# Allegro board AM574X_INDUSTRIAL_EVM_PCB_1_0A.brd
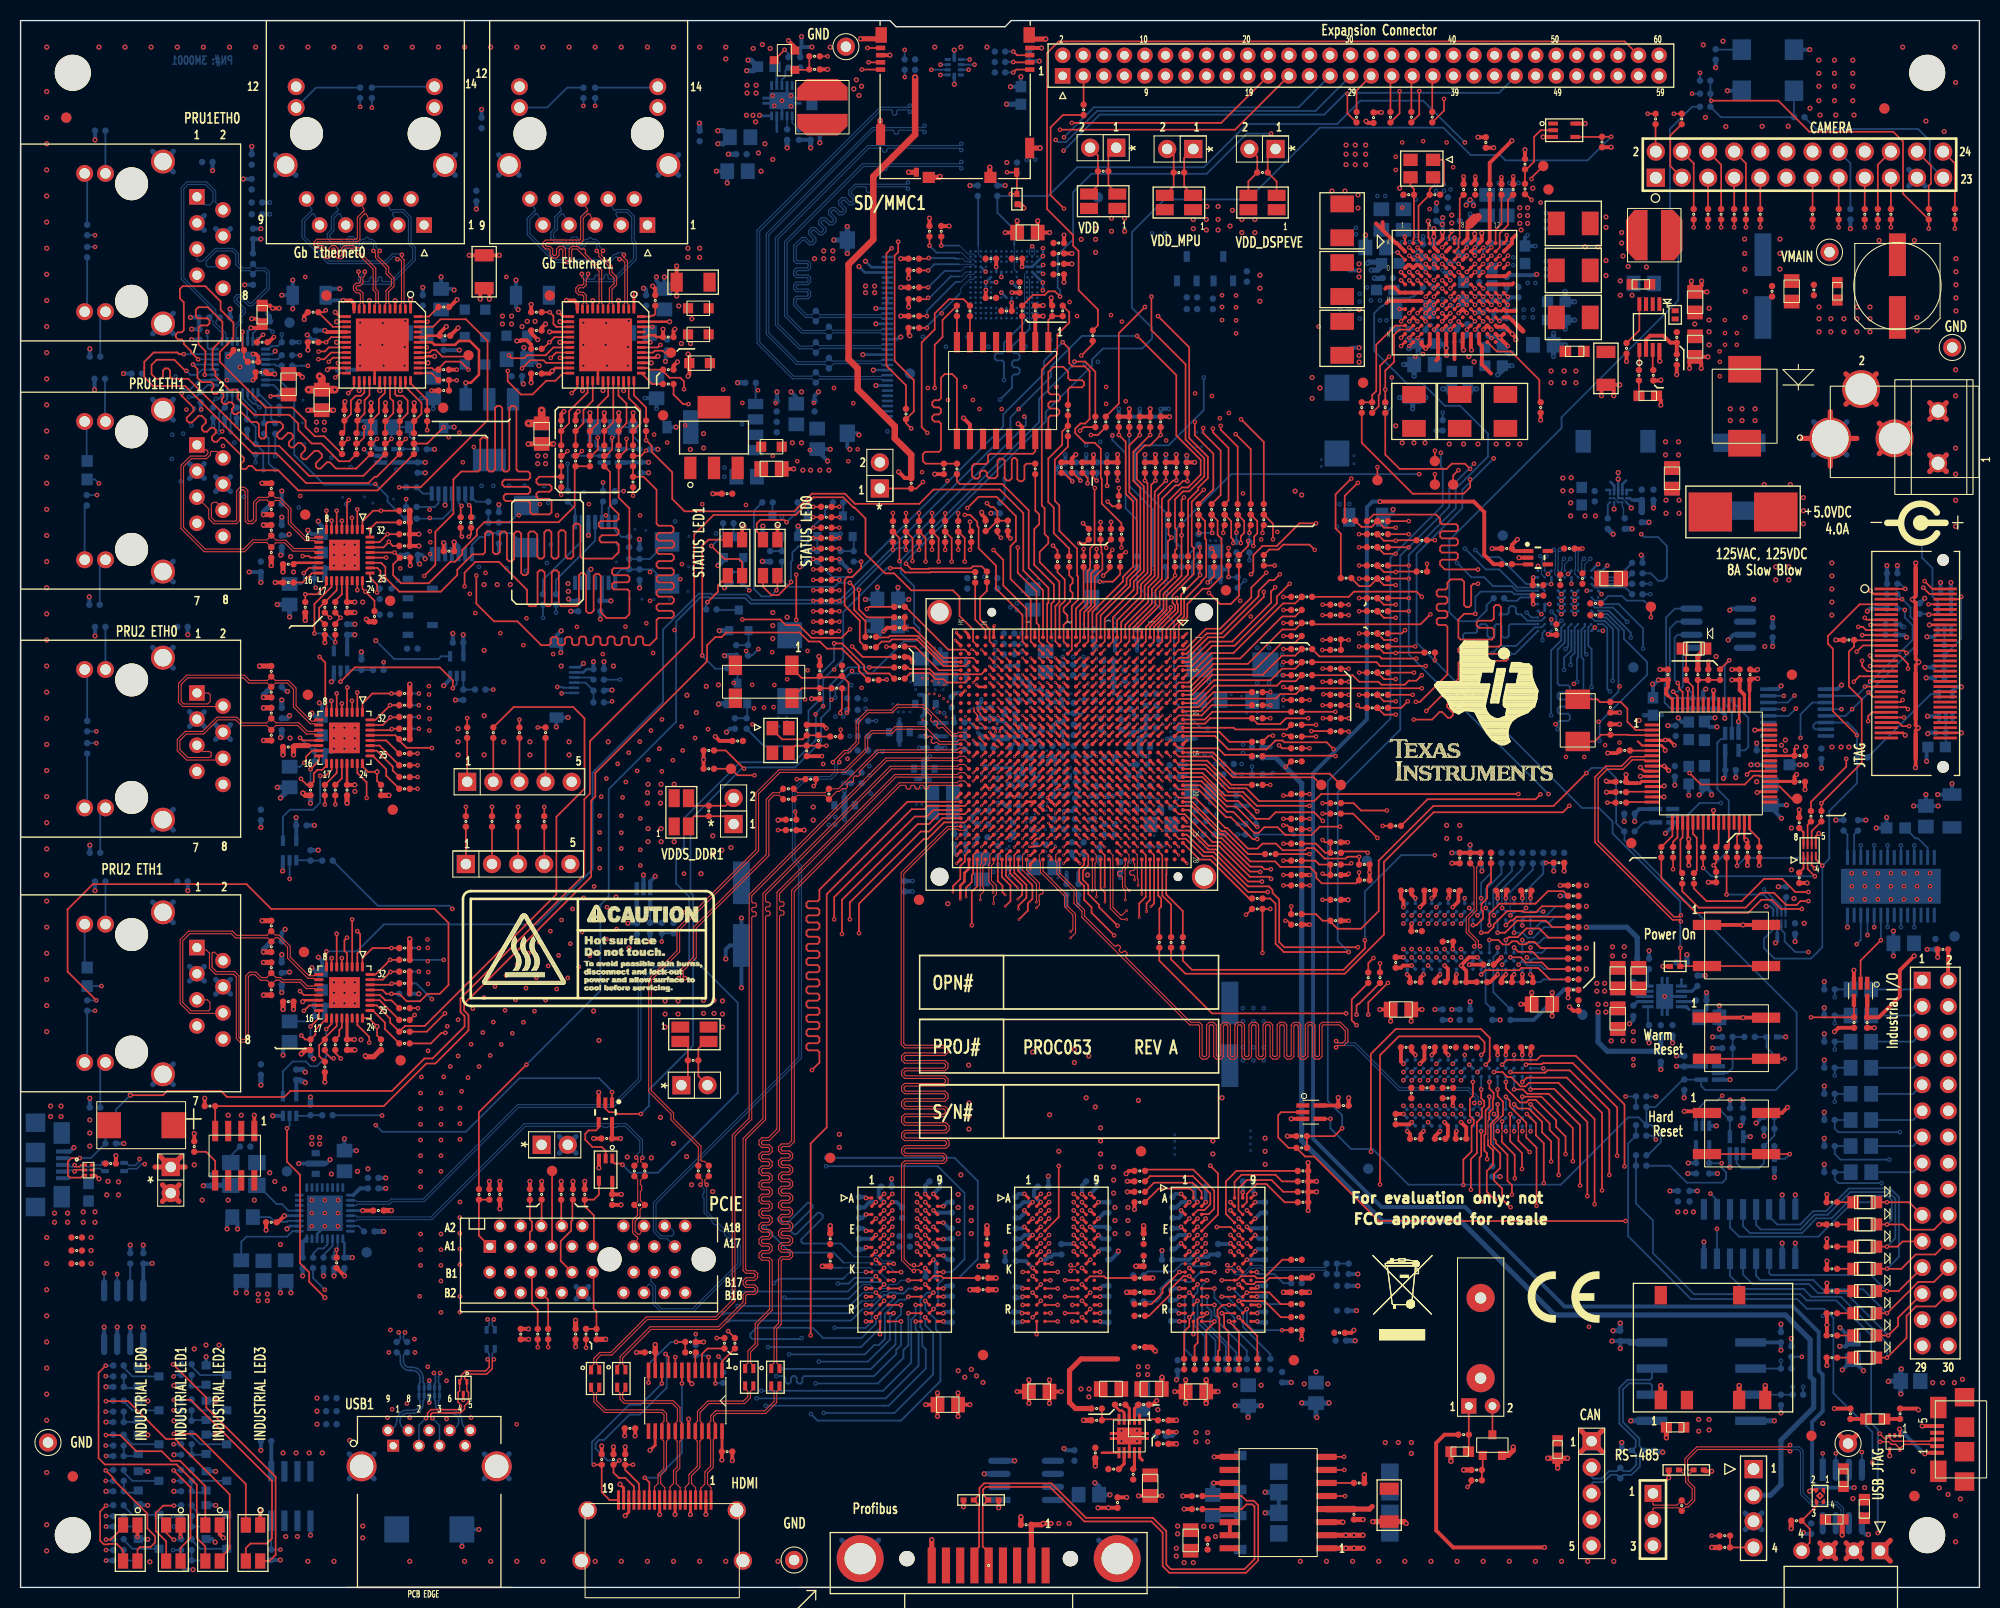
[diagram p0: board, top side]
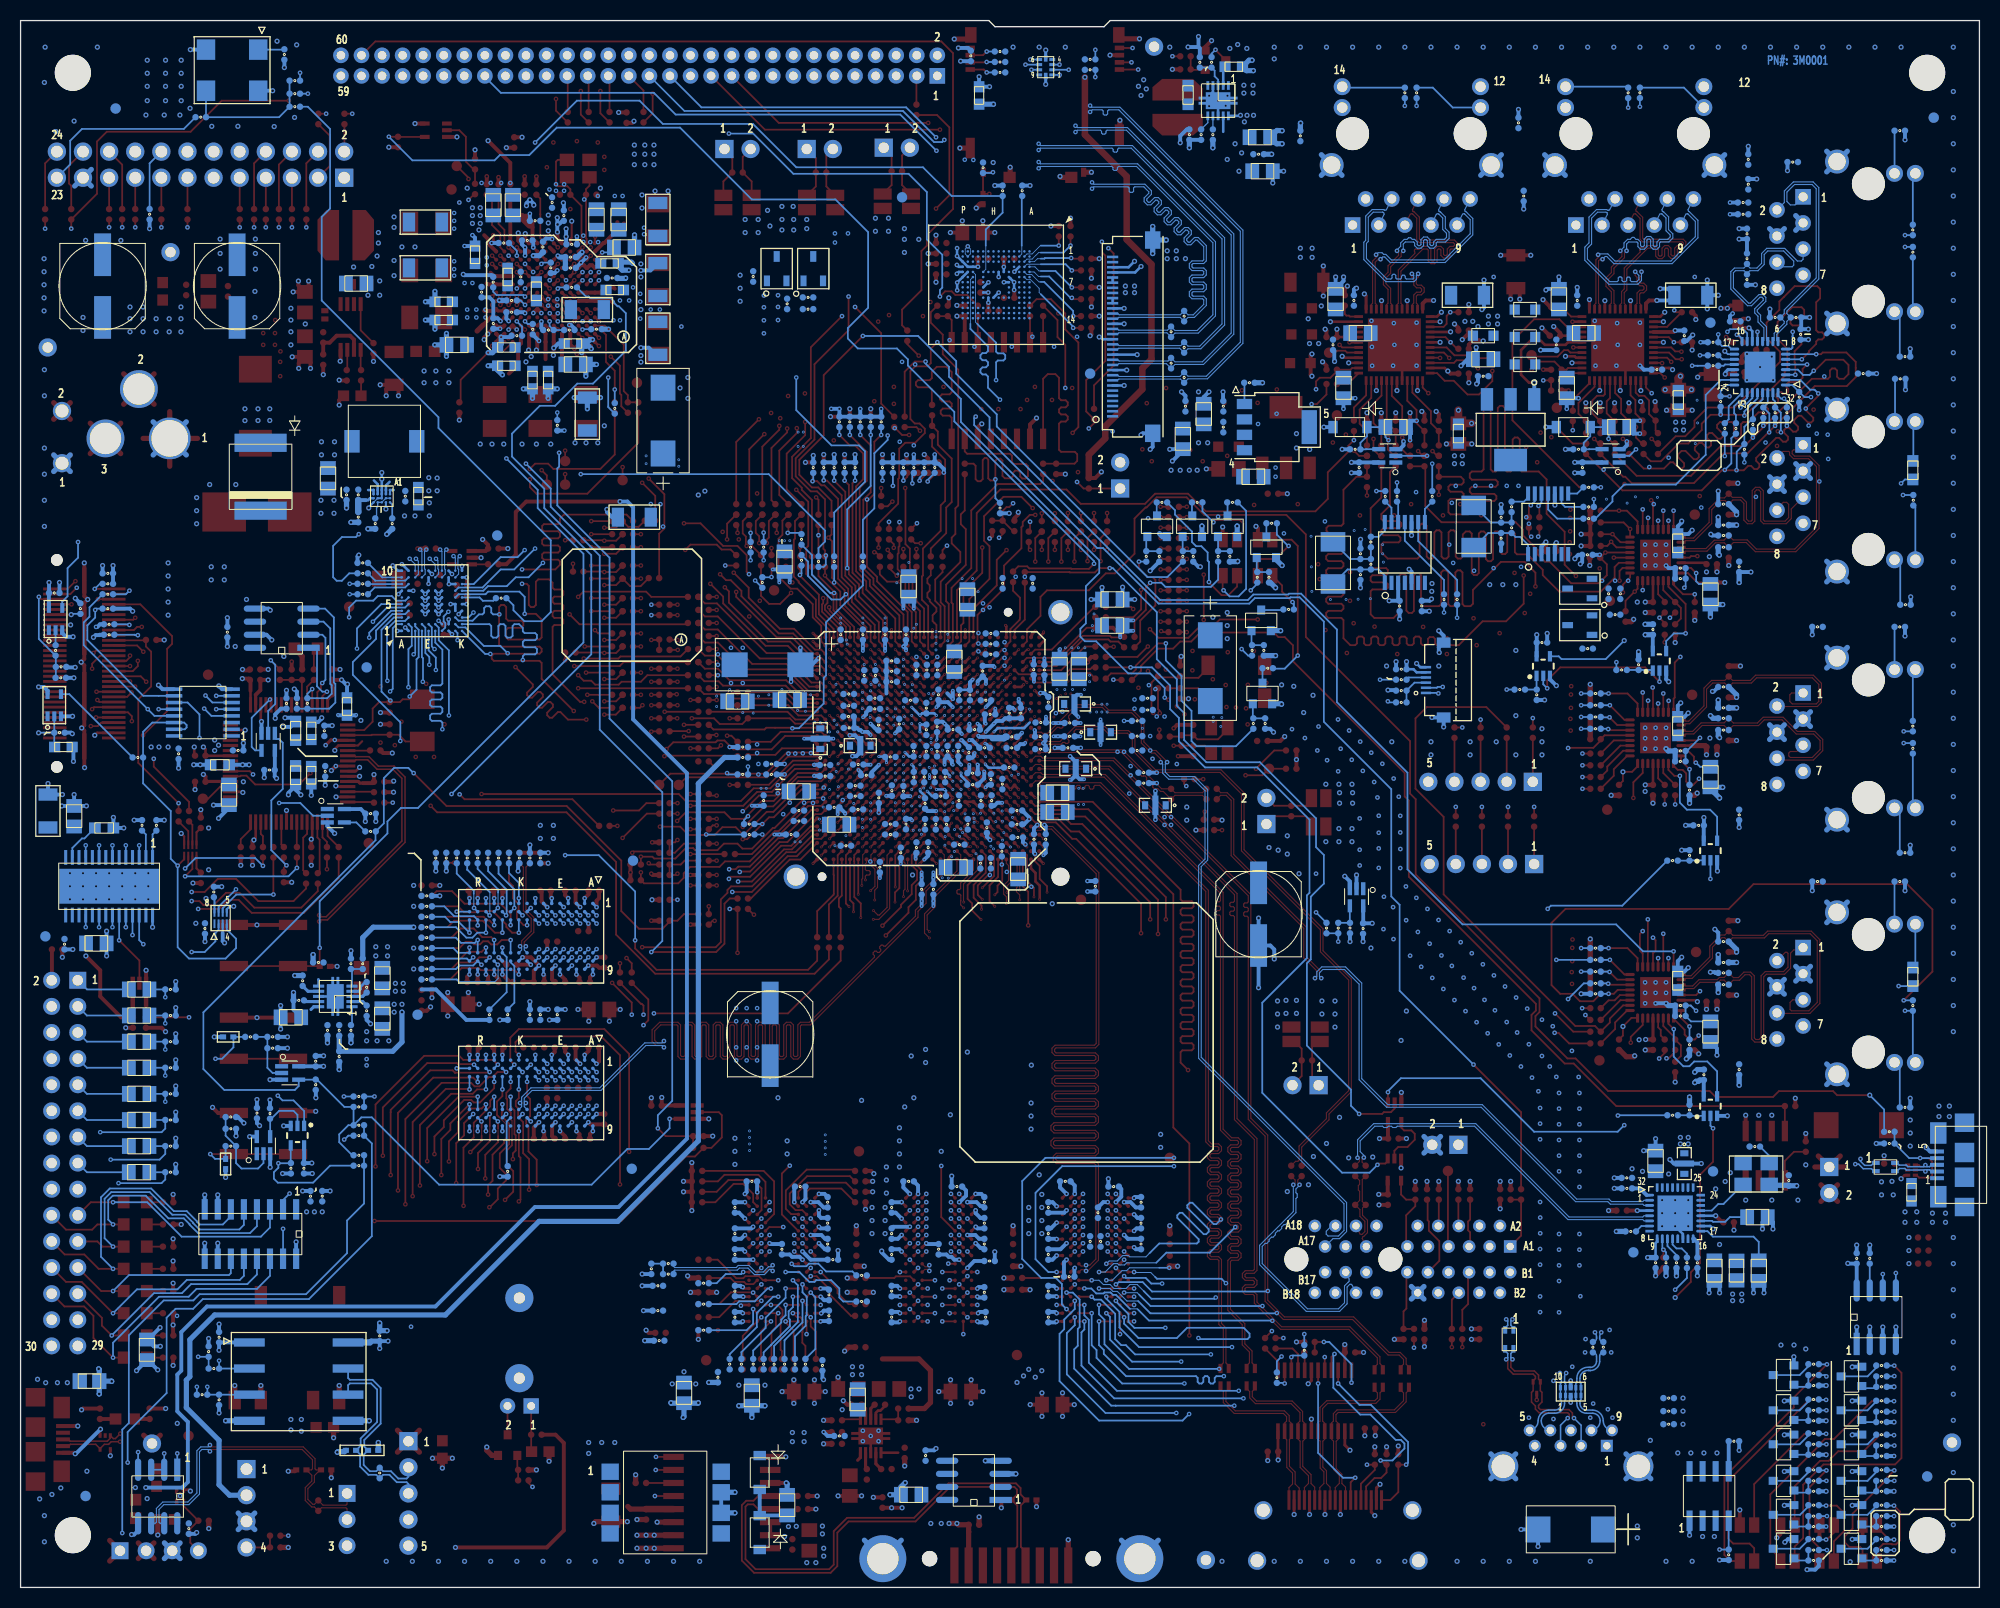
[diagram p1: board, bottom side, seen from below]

Outline 190.5 x 152.4 mm; copper layers: TOP, L2_GND1, L3_SIG1, L4_SIG2, L5_GND2, L6_PWR1, L7_PWR2, L8_GND3, L9_SIG3, L10_SIG4, L11_GND4, BOTTOM. Coordinates in mm from the lower left corner of the outline.
Outline path: 0,152.4 0,0 190.5,0 190.5,152.4 96.34,152.4 95.74,151.8 85.14,151.8 84.54,152.4 0,152.4

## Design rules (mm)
net group AM57XX_HDMI_CLK+: nets AM57XX_HDMI_CLK+ HDMI_CLK+
net group AM57XX_HDMI_CLK-: nets AM57XX_HDMI_CLK- HDMI_CLK-
net group AM57XX_HDMI_TX0+: nets AM57XX_HDMI_TX0+ HDMI_TX0+
net group AM57XX_HDMI_TX0-: nets AM57XX_HDMI_TX0- HDMI_TX0-
net group AM57XX_HDMI_TX1+: nets AM57XX_HDMI_TX1+ HDMI_TX1+
net group AM57XX_HDMI_TX1-: nets AM57XX_HDMI_TX1- HDMI_TX1-
net group AM57XX_HDMI_TX2+: nets AM57XX_HDMI_TX2+ HDMI_TX2+
net group AM57XX_HDMI_TX2-: nets AM57XX_HDMI_TX2- HDMI_TX2-
net group AM57XX_LCD_DE: nets AM57XX_LCD_DE LCD_DEN
net group AM57XX_LCD_HSYNC: nets AM57XX_LCD_HSYNC LCD_HS
net group AM57XX_LCD_PCLK: nets AM57XX_LCD_PCLK LCD_PCLK
net group AM57XX_LCD_VSYNC: nets AM57XX_LCD_VSYNC LCD_VS
net group AM57XX_MMC1_CLK: nets AM57XX_MMC1_CLK MMC_CLK
net group AM57XX_MMC1_CMD: nets AM57XX_MMC1_CMD MMC_CMD
net group AM57XX_MMC1_DAT0: nets AM57XX_MMC1_DAT0 MMC_D0
net group AM57XX_MMC1_DAT1: nets AM57XX_MMC1_DAT1 MMC_D1
net group AM57XX_MMC1_DAT2: nets AM57XX_MMC1_DAT2 MMC_D2
net group AM57XX_MMC1_DAT3: nets AM57XX_MMC1_DAT3 MMC_D3
net group AM57XX_PCIE_PER0: nets AM57XX_PCIE_PERN0 AM57XX_PCIE_PERP0
net group AM57XX_PCIE_PET0: nets AM57XX_PCIE_PETN0 AM57XX_PCIE_PETP0
net group AM57XX_PRU1ETH0_MRCLK: nets AM57XX_PRU1ETH0_MRCLK PRU1ETH0_RXCLK
net group AM57XX_PRU1ETH0_RXDV: nets AM57XX_PRU1ETH0_RXDV PRU1ETH0_RXDV
net group AM57XX_PRU1ETH1_TXCLK: nets AM57XX_PRU1ETH1_TXCLK PRU1ETH1_TXCLK
net group AM57XX_PRU1ETH1_TXD2: nets AM57XX_PRU1ETH1_TXD2 PRU1ETH1_TXD2
net group AM57XX_PRU1ETH1_TXD3: nets AM57XX_PRU1ETH1_TXD3 PRU1ETH1_TXD3
net group AM57XX_PRU1ETH1_TXEN: nets AM57XX_PRU1ETH1_TXEN PRU1ETH1_TXEN
net group AM57XX_PRU2ETH0_CRS: nets AM57XX_PRU2ETH0_CRS PRU2ETH0_CRS
net group AM57XX_PRU2ETH0_MRCLK: nets AM57XX_PRU2ETH0_MRCLK PRU2ETH0_RXCLK
net group AM57XX_PRU2ETH0_RXD0: nets AM57XX_PRU2ETH0_RXD0 PRU2ETH0_RXD0
net group AM57XX_PRU2ETH0_RXD1: nets AM57XX_PRU2ETH0_RXD1 PRU2ETH0_RXD1
net group AM57XX_PRU2ETH0_RXD2: nets AM57XX_PRU2ETH0_RXD2 PRU2ETH0_RXD2
net group AM57XX_PRU2ETH0_RXD3: nets AM57XX_PRU2ETH0_RXD3 PRU2ETH0_RXD3
net group AM57XX_PRU2ETH0_RXDV: nets AM57XX_PRU2ETH0_RXDV PRU2ETH0_RXDV
net group AM57XX_PRU2ETH0_RXER: nets AM57XX_PRU2ETH0_RXER PRU2ETH0_RXERR
net group AM57XX_PRU2ETH0_TXCLK: nets AM57XX_PRU2ETH0_TXCLK PRU2ETH0_TXCLK
net group AM57XX_PRU2ETH0_TXD0: nets AM57XX_PRU2ETH0_TXD0 PRU2ETH0_TXD0
net group AM57XX_PRU2ETH0_TXD1: nets AM57XX_PRU2ETH0_TXD1 PRU2ETH0_TXD1
net group AM57XX_PRU2ETH0_TXD2: nets AM57XX_PRU2ETH0_TXD2 PRU2ETH0_TXD2
net group AM57XX_PRU2ETH0_TXD3: nets AM57XX_PRU2ETH0_TXD3 PRU2ETH0_TXD3
net group AM57XX_PRU2ETH0_TXEN: nets AM57XX_PRU2ETH0_TXEN PRU2ETH0_TXEN
net group AM57XX_PRU2ETH1_MRCLK: nets AM57XX_PRU2ETH1_MRCLK PRU2ETH1_RXCLK
net group AM57XX_PRU2ETH1_RXD0: nets AM57XX_PRU2ETH1_RXD0 PRU2ETH1_RXD0
net group AM57XX_PRU2ETH1_RXD1: nets AM57XX_PRU2ETH1_RXD1 PRU2ETH1_RXD1
net group AM57XX_PRU2ETH1_RXD2: nets AM57XX_PRU2ETH1_RXD2 PRU2ETH1_RXD2
net group AM57XX_PRU2ETH1_RXD3: nets AM57XX_PRU2ETH1_RXD3 PRU2ETH1_RXD3
net group AM57XX_PRU2ETH1_RXDV: nets AM57XX_PRU2ETH1_RXDV PRU2ETH1_RXDV
net group AM57XX_PRU2ETH1_RXER: nets AM57XX_PRU2ETH1_RXER PRU2ETH1_RXERR
net group AM57XX_PRU2ETH1_TXCLK: nets AM57XX_PRU2ETH1_TXCLK PRU2ETH1_TXCLK
net group AM57XX_PRU2ETH1_TXD0: nets AM57XX_PRU2ETH1_TXD0 PRU2ETH1_TXD0
net group AM57XX_PRU2ETH1_TXD1: nets AM57XX_PRU2ETH1_TXD1 PRU2ETH1_TXD1
net group AM57XX_PRU2ETH1_TXD2: nets AM57XX_PRU2ETH1_TXD2 PRU2ETH1_TXD2
net group AM57XX_PRU2ETH1_TXD3: nets AM57XX_PRU2ETH1_TXD3 PRU2ETH1_TXD3
net group AM57XX_PRU2ETH1_TXEN: nets AM57XX_PRU2ETH1_TXEN PRU2ETH1_TXEN
net group AM57XX_RGMII1_RD1: nets AM57XX_RGMII1_RD1 ETH1_RXD1
net group AM57XX_RGMII1_RD2: nets AM57XX_RGMII1_RD2 ETH1_RXD2
net group AM57XX_RTCK: nets AM57XX_RTCK RTCK
net group AM57XX_VOUT1_D0: nets AM57XX_VOUT1_D0 LCD_B0
net group AM57XX_VOUT1_D1: nets AM57XX_VOUT1_D1 LCD_B1
net group AM57XX_VOUT1_D8: nets AM57XX_VOUT1_D8 LCD_G0
net group AM57XX_VOUT1_D9: nets AM57XX_VOUT1_D9 LCD_G1
net group AM57XX_VOUT1_D16: nets AM57XX_VOUT1_D16 LCD_R0
net group AM57XX_VOUT1_D17: nets AM57XX_VOUT1_D17 LCD_R1
net group AM437X_USB1_D: nets AM572X_USB1_DM AM572X_USB1_DP
net group AM572X_QSPI_D1: nets AM572X_QSPI_D1 SPIMEM_D1
net group AM572X_VIN4B_DATA0: nets AM572X_VIN4B_DATA0 CAM1_DATA0
net group AM572X_VIN4B_DATA1: nets AM572X_VIN4B_DATA1 CAM1_DATA1
net group AM572X_VIN4B_DATA2: nets AM572X_VIN4B_DATA2 CAM1_DATA2
net group AM572X_VIN4B_DATA3: nets AM572X_VIN4B_DATA3 CAM1_DATA3
net group AM572X_VIN4B_DATA4: nets AM572X_VIN4B_DATA4 CAM1_DATA4
net group AM572X_VIN4B_DATA5: nets AM572X_VIN4B_DATA5 CAM1_DATA5
net group AM572X_VIN4B_DATA6: nets AM572X_VIN4B_DATA6 CAM1_DATA6
net group AM572X_VIN4B_DATA7: nets AM572X_VIN4B_DATA7 CAM1_DATA7
net group AM572X_VIN4B_HSYNC: nets AM572X_VIN4B_HSYNC CAM1_HSYNC
net group AM572X_VIN4B_PCLK: nets AM572X_VIN4B_PCLK CAM1_PCLK
net group AM572X_VIN4B_VSYNC: nets AM572X_VIN4B_VSYNC CAM1_VSYNC
net group ETH_MDIO_CLK: nets ETH_MDIO_CLK PRU1ETH0_COL
net group JTAG_TCK: nets JTAG_TCK TCK
net group PCI_CONN_REF: nets PCI_CONN_REFN PCI_CONN_REFP
net group PRU2ETH1_COL: nets N17596842 PRU2ETH1_COL
net group PRU2ETH1_CRS: nets N17596973 PRU2ETH1_CRS
net group SERDES_REF_CLK: nets SERDES_REF_CLKN SERDES_REF_CLKP
net group SPIMEM_CSN: nets AM572X_QSPI_CSN SPIMEM_CSN
net group SPIMEM_D0: nets AM572X_QSPI_D0 SPIMEM_D0
net group SPIMEM_D2: nets AM572X_QSPI_D2 SPIMEM_D2
net group SPIMEM_D3: nets AM572X_QSPI_D3 SPIMEM_D3
net group AM57XX_PRU1ETH1_MRCLK: nets AM57XX_PRU1ETH1_MRCLK ETH1_TXD3 PRU1ETH1_RXCLK
net group AM57XX_PRU1ETH1_TXD0: nets AM57XX_PRU1ETH1_TXD0 ETH1_TXEN PRU1ETH1_TXD0
net group AM57XX_PRU1ETH1_TXD1: nets AM57XX_PRU1ETH1_TXD1 ETH1_TXCLK PRU1ETH1_TXD1
net group AM57XX_PRU1ETH_MDCLK: nets AM57XX_PRU1ETH_MDCLK PRU1ETH0_MDC PRU1ETH1_MDC
net group AM57XX_PRU1ETH_MDDATA: nets AM57XX_PRU1ETH_MDDATA PRU1ETH0_MDIO PRU1ETH1_MDIO
net group AM57XX_PRU2ETH_MDCLK: nets AM57XX_PRU2ETH_MDCLK PRU2ETH0_MDC PRU2ETH1_MDC
net group AM57XX_PRU2ETH_MDDATA: nets AM57XX_PRU2ETH_MDDATA PRU2ETH0_MDIO PRU2ETH1_MDIO
net group AM57XX_RGMII0_RD0: nets AM57XX_RGMII0_RD0 ETH0_RXD0 PRU1ETH0_TXD0
net group AM57XX_RGMII0_RD1: nets AM57XX_RGMII0_RD1 ETH0_RXD1 PRU1ETH0_TXD1
net group AM57XX_RGMII0_RD2: nets AM57XX_RGMII0_RD2 ETH0_RXD2 PRU1ETH0_TXEN
net group AM57XX_RGMII0_RD3: nets AM57XX_RGMII0_RD3 ETH0_RXD3 PRU1ETH0_TXD2
net group AM57XX_RGMII0_RXCLK: nets AM57XX_RGMII0_RXCLK ETH0_RXCLK PRU1ETH0_TXCLK
net group AM57XX_RGMII0_RXCTL: nets AM57XX_RGMII0_RXCTL ETH0_RXDV PRU1ETH0_TXD3
net group AM57XX_RGMII0_TD0: nets AM57XX_RGMII0_TD0 ETH0_TXD0 PRU1ETH0_RXD0
net group AM57XX_RGMII0_TD1: nets AM57XX_RGMII0_TD1 ETH0_TXD1 PRU1ETH0_RXD1
net group AM57XX_RGMII0_TD2: nets AM57XX_RGMII0_TD2 ETH0_TXD2 PRU1ETH0_RXERR
net group AM57XX_RGMII0_TD3: nets AM57XX_RGMII0_TD3 ETH0_TXD3 PRU1ETH0_CRS
net group AM57XX_RGMII0_TXCLK: nets AM57XX_RGMII0_TXCLK ETH0_TXCLK PRU1ETH0_RXD3
net group AM57XX_RGMII0_TXCTL: nets AM57XX_RGMII0_TXCTL ETH0_TXEN PRU1ETH0_RXD2
net group AM57XX_RGMII1_RD0: nets AM57XX_RGMII1_RD0 ETH1_RXD0 PRU1ETH1_CRS
net group AM57XX_RGMII1_RD3: nets AM57XX_RGMII1_RD3 ETH1_RXD3 PRU1ETH1_RXERR
net group AM57XX_RGMII1_RXCLK: nets AM57XX_RGMII1_RXCLK ETH1_RXCLK PRU1ETH1_RXD1
net group AM57XX_RGMII1_RXCTL: nets AM57XX_RGMII1_RXCTL ETH1_RXDV PRU1ETH1_RXD0
net group AM57XX_RGMII1_TD0: nets AM57XX_RGMII1_TD0 ETH1_TXD0 PRU1ETH1_RXD2
net group AM57XX_RGMII1_TD1: nets AM57XX_RGMII1_TD1 ETH1_TXD1 PRU1ETH1_RXD3
net group AM57XX_RGMII1_TD2: nets AM57XX_RGMII1_TD2 ETH1_TXD2 PRU1ETH1_RXDV
net group AM57XX_VOUT1_D2: nets AM57XX_VOUT1_D2 EMU2 LCD_B2
net group AM57XX_VOUT1_D3: nets AM57XX_VOUT1_D3 EMU5 LCD_B3
net group AM57XX_VOUT1_D4: nets AM57XX_VOUT1_D4 EMU6 LCD_B4
net group AM57XX_VOUT1_D5: nets AM57XX_VOUT1_D5 EMU7 LCD_B5
net group AM57XX_VOUT1_D6: nets AM57XX_VOUT1_D6 EMU8 LCD_B6
net group AM57XX_VOUT1_D7: nets AM57XX_VOUT1_D7 EMU9 LCD_B7
net group AM57XX_VOUT1_D10: nets AM57XX_VOUT1_D10 EMU3 LCD_G2
net group AM57XX_VOUT1_D11: nets AM57XX_VOUT1_D11 EMU10 LCD_G3
net group AM57XX_VOUT1_D12: nets AM57XX_VOUT1_D12 EMU11 LCD_G4
net group AM57XX_VOUT1_D13: nets AM57XX_VOUT1_D13 EMU12 LCD_G5
net group AM57XX_VOUT1_D14: nets AM57XX_VOUT1_D14 EMU13 LCD_G6
net group AM57XX_VOUT1_D15: nets AM57XX_VOUT1_D15 EMU14 LCD_G7
net group AM57XX_VOUT1_D18: nets AM57XX_VOUT1_D18 EMU4 LCD_R2
net group AM57XX_VOUT1_D19: nets AM57XX_VOUT1_D19 EMU15 LCD_R3
net group AM57XX_VOUT1_D20: nets AM57XX_VOUT1_D20 EMU16 LCD_R4
net group AM57XX_VOUT1_D21: nets AM57XX_VOUT1_D21 EMU17 LCD_R5
net group AM57XX_VOUT1_D22: nets AM57XX_VOUT1_D22 EMU18 LCD_R6
net group AM57XX_VOUT1_D23: nets AM57XX_VOUT1_D23 EMU19 LCD_R7
net group CLK: nets AM57XX_CLKOUT3 AM57XX_OSC0_IN AM57XX_OSC0_OUT ETH0GB_25MHZCLK ETH1GB_25MHZCLK INDUS_INPUTCLK N17745710 N22642197 OSC0_OUT PRU1ETH0_25MHZCLK PRU1ETH1_25MHZCLK PRU2ETH0_25MHZCLK PRU2ETH1_25MHZCLK SRCCLK XTIN XTOUT
net group DDR_ADD: nets DDR_CKE
net group PRU2ETHER0_D: nets PRU2ETHER0_RDN PRU2ETHER0_RDP PRU2ETHER0_TDN PRU2ETHER0_TDP
net group PWR: nets ETH0_LDO_O N11219802 N11219922 N18915671 N18915723 N19923825 N19923832 N19923845 N19923851 N19923852 N19923865 N20287248 N21553219 N21553307 N21553371 N22644059 USB1_OVRCURN V5_0DFB VANA_OUT VLDO1_OUT VPP_CONN
net group SPIMEM_CLK: nets AM572X_QSPI_CLK AM572X_QSPI_RTCLK QSPI_CLK SPIMEM_CLK
nets with their own width: min track width 0.127; nets DGND
nets with their own width: min track width 0.381; nets VSDMMC

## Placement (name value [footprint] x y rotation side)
C1  24pF  [SM-7351-CAP-0402]  76.45 83.39 90 top
C1_1  DNI  [SM-7351-CAP-0603]  177.27 10.68 90 top
C2  24pF  [SM-7351-CAP-0402]  76.45 81.36 270 top
C2_1  DNI  [SM-7351-CAP-0603]  176.38 6.62 0 top
C3  0.01uF  [SM-7351-CAP-0402]  167.51 46.14 90 bottom
C4  1uF  [SM-7351-CAP-0402]  170.05 44.61 180 bottom
C5  1uF  [SM-7351-CAP-0402]  165.99 53.55 180 bottom
C6  10uF  [SM-7351-CAP-0805]  93.49 69.87 270 bottom
C7  0.01uF  [SM-7351-CAP-0402]  93.52 72.95 180 bottom
C8  0.01uF  [SM-7351-CAP-0402]  93.6 74.22 180 bottom
C9  0.01uF  [SM-7351-CAP-0402]  95.07 71.61 270 bottom
C10  0.01uF  [SM-7351-CAP-0402]  97.16 70.44 270 bottom
C11  0.01uF  [SM-7351-CAP-0402]  93.6 75.57 180 bottom
C12  0.01uF  [SM-7351-CAP-0402]  90.8 72.77 90 bottom
C13  10uF  [SM-7351-CAP-0805]  110.9 74.2 0 bottom
C14  0.01uF  [SM-7351-CAP-0402]  103.38 71.96 270 bottom
C15  0.01uF  [SM-7351-CAP-0402]  110.24 72.14 0 bottom
C16  0.01uF  [SM-7351-CAP-0402]  109.07 75.67 0 bottom
C17  0.01uF  [SM-7351-CAP-0402]  102.23 71.96 270 bottom
C20  0.1uF  [SM-7351-CAP-0402]  170.33 126.07 90 top
C21  0.1uF  [SM-7351-CAP-0402]  174.4 126.19 90 top
C22  10uF  [SM-7351-CAP-0805]  172.24 126.07 90 top
C23  1uF  [SM-7351-CAP-0603]  176.68 126.07 90 top
C24  100uF  [SM-7351-CAP-SMDCAN]  169.44 126.57 270 bottom
C25  27pF  [SM-7351-CAP-0402]  135 135.46 0 top
C26  27pF  [SM-7351-CAP-0402]  137.54 135.46 180 top
C27  0.1uF  [SM-7351-CAP-0402]  140.34 135.97 270 top
C28  0.01uF  [SM-7351-CAP-0402]  98.68 124.16 90 top
C29  0.01uF  [SM-7351-CAP-0402]  81.53 35.43 270 bottom
C30  0.01uF  [SM-7351-CAP-0402]  84.2 38.99 0 bottom
C31  0.01uF  [SM-7351-CAP-0402]  81.53 37.46 270 bottom
C32  0.01uF  [SM-7351-CAP-0402]  90.55 36.96 90 bottom
C33  22uF  [SM-7351-CAP-0805]  90.17 17.78 0 top
C34  0.01uF  [SM-7351-CAP-0402]  88.9 39.5 0 bottom
C35  0.01uF  [SM-7351-CAP-0402]  90.55 26.29 270 bottom
C36  0.01uF  [SM-7351-CAP-0402]  90.55 32.38 90 bottom
C37  0.01uF  [SM-7351-CAP-0402]  90.55 28.83 90 bottom
C38  0.01uF  [SM-7351-CAP-0402]  90.55 34.42 270 bottom
C39  0.01uF  [SM-7351-CAP-0402]  88.52 30.23 0 bottom
C40  0.01uF  [SM-7351-CAP-0402]  85.47 33.66 90 bottom
C41  0.01uF  [SM-7351-CAP-0402]  85.72 36.45 90 bottom
C42  0.01uF  [SM-7351-CAP-0402]  81.53 33.4 270 bottom
C43  0.01uF  [SM-7351-CAP-0402]  86.49 33.66 90 bottom
C44  0.1uF  [SM-7351-CAP-0402]  78.74 33.91 270 top
C45  0.1uF  [SM-7351-CAP-0402]  78.74 31.75 270 top
C46  0.1uF  [SM-7351-CAP-0402]  93.6 28.96 0 top
C47  0.1uF  [SM-7351-CAP-0402]  109.22 33.91 270 top
C48  0.01uF  [SM-7351-CAP-0402]  105.79 36.96 90 bottom
C49  0.01uF  [SM-7351-CAP-0402]  96.77 37.46 270 bottom
C50  0.01uF  [SM-7351-CAP-0402]  104.14 39.5 0 bottom
C51  0.01uF  [SM-7351-CAP-0402]  96.65 26.29 270 bottom
C52  22uF  [SM-7351-CAP-0805]  99.06 19.05 0 top
C53  0.1uF  [SM-7351-CAP-0402]  109.22 31.75 270 top
C54  0.1uF  [SM-7351-CAP-0402]  124.08 28.7 0 top
C55  0.01uF  [SM-7351-CAP-0402]  105.79 26.29 270 bottom
C56  0.01uF  [SM-7351-CAP-0402]  96.27 31.75 180 bottom
C57  0.01uF  [SM-7351-CAP-0402]  96.77 28.7 90 bottom
C58  0.01uF  [SM-7351-CAP-0402]  101.22 32.89 270 bottom
C59  0.01uF  [SM-7351-CAP-0402]  96.77 33.4 270 bottom
C60  0.01uF  [SM-7351-CAP-0402]  111.51 31.88 180 bottom
C61  0.01uF  [SM-7351-CAP-0402]  121.03 32.38 270 bottom
C62  0.01uF  [SM-7351-CAP-0402]  116.46 32.89 270 bottom
C63  0.01uF  [SM-7351-CAP-0402]  119.38 39.5 0 bottom
C64  22uF  [SM-7351-CAP-0805]  114.3 19.05 0 top
C65  0.01uF  [SM-7351-CAP-0402]  105.79 32.38 270 bottom
C66  0.01uF  [SM-7351-CAP-0402]  105.79 28.83 90 bottom
C67  0.01uF  [SM-7351-CAP-0402]  96.77 35.43 270 bottom
C68  0.01uF  [SM-7351-CAP-0402]  105.79 34.42 270 bottom
C69  0.01uF  [SM-7351-CAP-0402]  99.44 38.99 0 bottom
C70  0.01uF  [SM-7351-CAP-0402]  121.03 26.29 270 bottom
C71  0.01uF  [SM-7351-CAP-0402]  114.68 38.99 0 bottom
C72  0.01uF  [SM-7351-CAP-0402]  111.89 26.42 270 bottom
C73  0.01uF  [SM-7351-CAP-0402]  121.03 34.42 270 bottom
C74  0.01uF  [SM-7351-CAP-0402]  112.01 37.46 270 bottom
C75  0.01uF  [SM-7351-CAP-0402]  121.03 28.83 90 bottom
C76  0.01uF  [SM-7351-CAP-0402]  121.03 36.96 90 bottom
C77  0.01uF  [SM-7351-CAP-0402]  112.01 35.43 270 bottom
C78  0.01uF  [SM-7351-CAP-0402]  112.01 33.4 270 bottom
C79  0.01uF  [SM-7351-CAP-0402]  111.89 28.45 90 bottom
C80  0.1uF  [SM-7351-CAP-0402]  93.98 33.91 270 top
C81  0.01uF  [SM-7351-CAP-0402]  96.14 78.59 90 bottom
C82  0.1uF  [SM-7351-CAP-0402]  93.98 31.75 270 top
C83  0.1uF  [SM-7351-CAP-0402]  108.84 28.7 0 top
C84  0.001uF  [SM-7351-CAP-0402]  110.87 14.73 180 bottom
C85  0.1uF  [SM-7351-CAP-0402]  129.16 30.99 270 bottom
C86  0.001uF  [SM-7351-CAP-0402]  111.12 16.26 0 top
C87  0.1uF  [SM-7351-CAP-0402]  128.52 29.34 0 bottom
C88  10uF  [SM-7351-CAP-0805]  109.86 9.91 270 top
C89  0.1uF  [SM-7351-CAP-0402]  128.27 24.77 0 top
C90  0.1uF  [SM-7351-CAP-0402]  109.22 17.78 0 top
C91  10uF  [SM-7351-CAP-0805]  109.98 19.3 0 top
C92  10uF  [SM-7351-CAP-0805]  109.09 18.29 270 bottom
C93  0.1uF  [SM-7351-CAP-0402]  108.84 23.37 0 top
C94  0.1uF  [SM-7351-CAP-0402]  112.52 21.59 270 bottom
C95  10uF  [SM-7351-CAP-0805]  125.98 18.92 270 bottom
C96  10uF  [SM-7351-CAP-0805]  119.38 18.67 270 bottom
C97  10uF  [SM-7351-CAP-0805]  106.05 19.3 180 top
C98  0.1uF  [SM-7351-CAP-0402]  128.4 24 0 bottom
C99  0.1uF  [SM-7351-CAP-0402]  104.52 13.08 270 top
C100  0.1uF  [SM-7351-CAP-0402]  106.93 17.78 180 top
C101  10pF  [SM-7351-CAP-0402]  104.65 16.26 180 top
C102  0.1uF  [SM-7351-CAP-0402]  22.99 134.7 0 bottom
C103  0.1uF  [SM-7351-CAP-0402]  22.99 133.56 0 bottom
C104  0.1uF  [SM-7351-CAP-0402]  17.4 121.87 270 bottom
C105  0.01uF  [SM-7351-CAP-0402]  23.37 118.19 180 top
C106  4700pF  [SM-7351-CAP-0402]  18.16 138.64 180 bottom
C107  0.1uF  [SM-7351-CAP-0402]  22.61 131.65 90 bottom
C108  0.1uF  [SM-7351-CAP-0402]  25.17 115.35 270 bottom
C109  0.1uF  [SM-7351-CAP-0402]  22.61 119.21 0 top
C110  10uF  [SM-7351-CAP-0805]  26.06 117.02 90 top
C111  0.1uF  [SM-7351-CAP-0402]  21.21 120.35 180 top
C112  0.01uF  [SM-7351-CAP-0402]  23.75 123.14 0 bottom
C113  0.01uF  [SM-7351-CAP-0402]  42.55 91.9 180 bottom
C114  0.01uF  [SM-7351-CAP-0402]  97.92 79.2 180 bottom
C115  0.01uF  [SM-7351-CAP-0402]  96.14 70.44 270 bottom
C116  0.1uF  [SM-7351-CAP-0402]  24.89 102.32 0 bottom
C117  0.1uF  [SM-7351-CAP-0402]  24.89 101.17 0 bottom
C118  0.01uF  [SM-7351-CAP-0402]  26.03 99.52 180 top
C119  0.1uF  [SM-7351-CAP-0402]  24.89 105.36 0 bottom
C120  0.01uF  [SM-7351-CAP-0402]  31.75 95.33 270 top
C121  4700pF  [SM-7351-CAP-0402]  11.3 118.06 0 bottom
C122  0.1uF  [SM-7351-CAP-0402]  24.89 103.33 0 bottom
C123  0.1uF  [SM-7351-CAP-0402]  34.42 94.44 270 top
C124  0.1uF  [SM-7351-CAP-0402]  29.08 99.14 0 bottom
C125  10uF  [SM-7351-CAP-0805]  26.16 96.6 270 bottom
C126  0.1uF  [SM-7351-CAP-0402]  29.08 98.13 0 bottom
C127  0.01uF  [SM-7351-CAP-0402]  31.75 93.17 90 bottom
C128  0.1uF  [SM-7351-CAP-0402]  24.89 84.54 0 bottom
C129  0.1uF  [SM-7351-CAP-0402]  24.89 83.39 0 bottom
C130  0.01uF  [SM-7351-CAP-0402]  31.75 77.55 270 top
C131  4700pF  [SM-7351-CAP-0402]  15.75 93.43 180 bottom
C132  0.1uF  [SM-7351-CAP-0402]  24.89 85.55 0 bottom
C133  0.1uF  [SM-7351-CAP-0402]  24.89 87.58 0 bottom
C134  0.1uF  [SM-7351-CAP-0402]  29.08 80.35 0 bottom
C135  0.1uF  [SM-7351-CAP-0402]  35.05 77.55 270 top
C136  10uF  [SM-7351-CAP-0805]  26.16 78.82 270 bottom
C137  0.01uF  [SM-7351-CAP-0402]  26.03 81.74 180 top
C138  0.1uF  [SM-7351-CAP-0402]  29.08 81.36 0 bottom
C139  0.01uF  [SM-7351-CAP-0402]  27.3 74.12 0 bottom
C140  0.1uF  [SM-7351-CAP-0402]  24.89 59.77 0 bottom
C141  0.1uF  [SM-7351-CAP-0402]  24.89 58.63 0 bottom
C142  0.01uF  [SM-7351-CAP-0402]  26.03 56.98 180 top
C143  0.1uF  [SM-7351-CAP-0402]  24.89 60.79 0 bottom
C144  0.01uF  [SM-7351-CAP-0402]  31.75 52.79 270 top
C145  0.1uF  [SM-7351-CAP-0402]  24.89 62.82 0 bottom
C146  4700pF  [SM-7351-CAP-0402]  15.75 68.66 180 bottom
C147  0.1uF  [SM-7351-CAP-0402]  35.05 52.79 270 top
C148  0.1uF  [SM-7351-CAP-0402]  29.08 56.6 0 bottom
C149  10uF  [SM-7351-CAP-0805]  26.16 54.06 270 bottom
C150  0.1uF  [SM-7351-CAP-0402]  29.08 55.58 0 bottom
C151  0.01uF  [SM-7351-CAP-0402]  26.8 49.87 90 bottom
C152  0.01uF  [SM-7351-CAP-0402]  131.57 142.96 90 top
C153  0.1uF  [SM-7351-CAP-0402]  48.26 117.81 0 bottom
C154  10uF  [SM-7351-CAP-0805]  48.26 119.46 0 bottom
C155  0.1uF  [SM-7351-CAP-0402]  28.7 121.75 270 bottom
C156  10uF  [SM-7351-CAP-0805]  29.29 115.5 270 top
C157  47uF  [SM-7351-CAP-1206]  28.07 125.68 0 bottom
C158  47uF  [SM-7351-CAP-1206]  45.09 127.97 270 top
C159  10uF  [SM-7351-CAP-0805]  40.13 116.67 270 bottom
C160  0.1uF  [SM-7351-CAP-0402]  31.37 118.45 0 bottom
C161  10uF  [SM-7351-CAP-0805]  40.89 125.3 90 bottom
C162  0.1uF  [SM-7351-CAP-0402]  39.12 125.18 90 bottom
C163  10uF  [SM-7351-CAP-0805]  38.48 122 180 bottom
C164  0.1uF  [SM-7351-CAP-0402]  41.15 120.86 270 bottom
C165  0.01uF  [SM-7351-CAP-0402]  41.27 121.75 0 top
C166  0.1uF  [SM-7351-CAP-0402]  22.48 138.89 270 bottom
C167  0.1uF  [SM-7351-CAP-0402]  44.32 135.34 90 bottom
C168  10uF  [SM-7351-CAP-0805]  35.05 112.86 180 bottom
C169  0.01uF  [SM-7351-CAP-0402]  41.66 100.79 180 top
C170  0.01uF  [SM-7351-CAP-0402]  38.13 100.44 180 bottom
C171  0.01uF  [SM-7351-CAP-0402]  38.61 108.92 270 bottom
C172  18pF  [SM-7351-CAP-0402]  46.51 102.05 90 bottom
C173  18pF  [SM-7351-CAP-0402]  46.51 104.08 270 bottom
C174  0.1uF  [SM-7351-CAP-0402]  50.16 122.26 180 top
C175  10uF  [SM-7351-CAP-0805]  50.67 112.22 270 top
C176  0.1uF  [SM-7351-CAP-0402]  68.71 106.38 180 top
C177  10uF  [SM-7351-CAP-0805]  73.02 108.79 0 top
C178  47uF  [SM-7351-CAP-1206]  49.78 125.68 0 bottom
C179  47uF  [SM-7351-CAP-1206]  65.41 126.95 0 top
C180  10uF  [SM-7351-CAP-0805]  61.85 116.67 270 bottom
C181  0.1uF  [SM-7351-CAP-0402]  50.16 118.06 180 top
C182  10uF  [SM-7351-CAP-0805]  62.61 125.3 90 bottom
C183  0.1uF  [SM-7351-CAP-0402]  60.83 125.18 90 bottom
C184  10uF  [SM-7351-CAP-0805]  60.2 122 180 bottom
C185  0.1uF  [SM-7351-CAP-0402]  62.86 120.86 270 bottom
C186  0.01uF  [SM-7351-CAP-0402]  62.99 121.62 0 top
C187  0.1uF  [SM-7351-CAP-0402]  44.83 142.45 270 bottom
C188  0.1uF  [SM-7351-CAP-0402]  66.04 141.18 270 bottom
C189  10uF  [SM-7351-CAP-0805]  56.77 112.86 180 bottom
C190  0.01uF  [SM-7351-CAP-0402]  56.39 95.46 270 bottom
C191  0.01uF  [SM-7351-CAP-0402]  54.23 95.46 270 bottom
C192  0.01uF  [SM-7351-CAP-0402]  60.32 108.92 270 bottom
C193  18pF  [SM-7351-CAP-0402]  60.2 98.51 90 bottom
C194  18pF  [SM-7351-CAP-0402]  60.2 100.54 270 bottom
C195  0.01uF  [SM-7351-CAP-0402]  179.58 54.95 270 top
C196  0.001uF  [SM-7351-CAP-0402]  186.94 62.06 180 top
C197  22nF  [SM-7351-CAP-0402]  175.92 58.17 180 bottom
C198  22nF  [SM-7351-CAP-0402]  175.92 55.63 180 bottom
C199  22nF  [SM-7351-CAP-0402]  175.92 53.09 180 bottom
C200  22nF  [SM-7351-CAP-0402]  175.92 50.55 180 bottom
C201  22nF  [SM-7351-CAP-0402]  175.92 48.01 180 bottom
C202  22nF  [SM-7351-CAP-0402]  175.92 45.47 180 bottom
C203  22nF  [SM-7351-CAP-0402]  175.92 42.93 180 bottom
C204  22nF  [SM-7351-CAP-0402]  175.92 40.39 180 bottom
C205  2.2uF  [SM-7351-CAP-0805]  183.13 62.65 180 bottom
C206  10uF  [SM-7351-CAP-1206]  187.83 75.52 270 bottom
C207  0.01uF  [SM-7351-CAP-0402]  186.23 62.57 270 bottom
C208  2.2uF  [SM-7351-CAP-0805]  178.21 23.11 90 bottom
C209  1uF  [SM-7351-CAP-0402]  161.16 38.05 90 bottom
C210  0.01uF  [SM-7351-CAP-0402]  162.31 38.05 90 bottom
C211  0.1uF  [SM-7351-CAP-0402]  98.08 148.96 270 bottom
C212  4.7uF  [SM-7351-CAP-0603]  97.28 145.12 270 bottom
C213  0.1uF  [SM-7351-CAP-0402]  164.21 40.77 270 bottom
C214  0.01uF  [SM-7351-CAP-0402]  128.65 46.86 0 top
C215  10uF  [SM-7351-CAP-0805]  69.72 137.75 180 bottom
C216  0.01uF  [SM-7351-CAP-0402]  70.1 139.4 180 bottom
C217  4.7uF  [SM-7351-CAP-0603]  72.52 147.91 180 bottom
C218  4.7uF  [SM-7351-CAP-0805]  69.98 141.05 180 bottom
C219  0.01uF  [SM-7351-CAP-0402]  56.22 89.31 0 bottom
C220  0.01uF  [SM-7351-CAP-0402]  11.94 32 90 bottom
C221  0.01uF  [SM-7351-CAP-0402]  182.02 98.63 0 bottom
C222  10uF  [SM-7351-CAP-0805]  77.47 111.71 270 bottom
C223  DNI  [SM-7351-CAP-0402]  186.56 89.53 180 bottom
C224  2.2uF  [SM-7351-CAP-0805]  170.23 77.09 270 bottom
C225  0.01uF  [SM-7351-CAP-0402]  182.78 16.89 90 top
C226  0.01uF  [SM-7351-CAP-0402]  177.95 16.89 90 top
C227  0.01uF  [SM-7351-CAP-0402]  173.02 78.36 0 top
C228  0.01uF  [SM-7351-CAP-0402]  166.29 79.51 180 bottom
C229  0.01uF  [SM-7351-CAP-0402]  167.94 71.51 270 top
C230  0.01uF  [SM-7351-CAP-0402]  156.46 75.27 0 bottom
C231  4.7uF  [SM-7351-CAP-0603]  162.23 83.32 270 bottom
C232  0.01uF  [SM-7351-CAP-0402]  168.2 88.78 90 top
C233  0.01uF  [SM-7351-CAP-0402]  173.02 80.9 0 top
C234  0.01uF  [SM-7351-CAP-0402]  160.96 83.32 270 bottom
C235  0.01uF  [SM-7351-CAP-0402]  160.2 88.78 90 top
C236  0.01uF  [SM-7351-CAP-0402]  164.64 85.98 270 bottom
C237  4.7uF  [SM-7351-CAP-0603]  162.23 79 90 bottom
C238  0.01uF  [SM-7351-CAP-0402]  155.63 78.36 180 top
C239  0.01uF  [SM-7351-CAP-0402]  162.23 71.51 270 top
C240  0.01uF  [SM-7351-CAP-0402]  160.87 79.38 90 bottom
C241  4.7uF  [SM-7351-CAP-0603]  158.75 85.68 270 bottom
C242  0.01uF  [SM-7351-CAP-0402]  167.18 88.78 270 top
C243  18pF  [SM-7351-CAP-0402]  154.61 85.6 270 top
C244  18pF  [SM-7351-CAP-0402]  154.61 83.44 90 top
C245  0.1uF  [SM-7351-CAP-0402]  170.39 92.92 90 bottom
C246  15pF  [SM-7351-CAP-0402]  77.72 89.15 90 top
C247  15pF  [SM-7351-CAP-0402]  77.72 86.95 270 top
C248  0.01uF  [SM-7351-CAP-0402]  59.94 64.09 270 bottom
C249  3.3uF  [SM-7351-CAP-0603]  160.91 15.58 180 top
C250  3.3uF  [SM-7351-CAP-0603]  149.48 13.42 270 top
C251  0.01uF  [SM-7351-CAP-0402]  171.2 24.34 90 bottom
C252  0.1uF  [SM-7351-CAP-0402]  155.58 24.47 90 bottom
C253  100pF  [SM-7351-CAP-0402]  172.21 22.94 90 bottom
C254  100pF  [SM-7351-CAP-0402]  171.2 18.24 270 bottom
C255  0.01uF  [SM-7351-CAP-0402]  94.36 125.43 0 top
C256  0.01uF  [SM-7351-CAP-0402]  95.89 124.16 180 top
C257  0.01uF  [SM-7351-CAP-0402]  94.36 129.24 180 top
C258  0.01uF  [SM-7351-CAP-0402]  97.16 126.45 90 top
C261  0.01uF  [SM-7351-CAP-0402]  100.97 128.73 0 top
C262  0.01uF  [SM-7351-CAP-0402]  100.97 129.75 0 top
C263  0.01uF  [SM-7351-CAP-0402]  100.97 130.76 0 top
C264  0.01uF  [SM-7351-CAP-0402]  100.97 127.72 0 top
C265  1uF  [SM-7351-CAP-0402]  93.09 135.84 90 bottom
C266  10uF  [SM-7351-CAP-0805]  89.46 89.34 90 bottom
C267  0.01uF  [SM-7351-CAP-0402]  99.21 86.8 90 bottom
C268  47uF  [SM-7351-CAP-1206]  135.38 114.13 270 bottom
C269  47uF  [SM-7351-CAP-1206]  128.52 133.05 90 bottom
C270  47uF  [SM-7351-CAP-1206]  130.81 104.09 0 bottom
C271  47uF  [SM-7351-CAP-1206]  135.38 124.29 0 bottom
C272  4.7uF  [SM-7351-CAP-0603]  136.78 120.99 180 bottom
C273  4.7uF  [SM-7351-CAP-0603]  132.72 126.19 180 bottom
C274  4.7uF  [SM-7351-CAP-0603]  143.26 120.6 0 bottom
C275  4.7uF  [SM-7351-CAP-0603]  143.26 118.83 0 bottom
C276  47uF  [SM-7351-CAP-1206]  151.13 132.8 0 bottom
C277  47uF  [SM-7351-CAP-1206]  151.13 128.35 0 bottom
C278  47uF  [SM-7351-CAP-1206]  154.18 118.57 90 top
C279  47uF  [SM-7351-CAP-1206]  128.52 127.21 90 bottom
C280  47uF  [SM-7351-CAP-1206]  128.52 121.49 270 bottom
C281  4.7uF  [SM-7351-CAP-0603]  146.3 129.62 90 bottom
C282  4.7uF  [SM-7351-CAP-0603]  149.35 123.27 0 bottom
C283  4.7uF  [SM-7351-CAP-0603]  149.35 125.05 0 bottom
C284  4.7uF  [SM-7351-CAP-0603]  133.22 128.78 180 bottom
C285  4.7uF  [SM-7351-CAP-0603]  140.72 117.43 270 bottom
C286  1uF  [SM-7351-CAP-0402]  110.74 92.66 90 bottom
C287  1uF  [SM-7351-CAP-0402]  108.58 92.66 90 bottom
C288  1uF  [SM-7351-CAP-0402]  109.04 80.04 0 bottom
C289  1uF  [SM-7351-CAP-0402]  115.57 73.23 0 bottom
C290  1uF  [SM-7351-CAP-0402]  106.43 92.66 90 bottom
C291  1uF  [SM-7351-CAP-0402]  108.25 79 0 bottom
C292  1uF  [SM-7351-CAP-0402]  118.24 76.54 270 bottom
C293  1uF  [SM-7351-CAP-0402]  104.39 92.66 90 bottom
C294  1uF  [SM-7351-CAP-0402]  102.54 76.26 270 bottom
C295  1uF  [SM-7351-CAP-0402]  102.87 67.9 270 bottom
C296  1uF  [SM-7351-CAP-0402]  101.73 67.9 270 bottom
C297  1uF  [SM-7351-CAP-0402]  94.11 82.73 180 bottom
C298  1uF  [SM-7351-CAP-0402]  91.34 82.76 180 bottom
C299  1uF  [SM-7351-CAP-0402]  88.47 84.08 180 bottom
C300  1uF  [SM-7351-CAP-0402]  94.36 79.76 180 bottom
C301  2.2uF  [SM-7351-CAP-0402]  141.48 135.97 90 top
C302  2.2uF  [SM-7351-CAP-0402]  139.7 130.38 90 bottom
C303  0.1uF  [SM-7351-CAP-0402]  48.64 24.64 270 top
C304  0.1uF  [SM-7351-CAP-0402]  46.61 38.23 90 top
C305  10uF  [SM-7351-CAP-0805]  21.46 30.82 270 bottom
C306  10uF  [SM-7351-CAP-0805]  21.59 36.02 180 bottom
C307  10uF  [SM-7351-CAP-0805]  25.78 30.82 270 bottom
C308  0.01uF  [SM-7351-CAP-0402]  24.38 35.51 180 top
C309  0.01uF  [SM-7351-CAP-0402]  27.43 31.58 270 bottom
C310  0.01uF  [SM-7351-CAP-0402]  31.5 31.58 270 bottom
C311  150uF  [SM-7351-CAP-2917]  39.75 5.64 180 bottom
C313  0.1uF  [SM-7351-CAP-0402]  122.68 20.45 270 bottom
C314  0.1uF  [SM-7351-CAP-0402]  128.52 26.92 0 bottom
C315  0.01uF  [SM-7351-CAP-0402]  77.22 114.89 90 bottom
C316  1uF  [SM-7351-CAP-0603]  139.95 13.21 180 top
C317  10uF  [SM-7351-CAP-0805]  148.08 120.86 0 bottom
C318  2.2uF  [SM-7351-CAP-0402]  140.46 132.92 0 bottom
C319  0.01uF  [SM-7351-CAP-0402]  187.22 96.73 180 bottom
C320  10uF  [SM-7351-CAP-0805]  31.5 41.48 90 bottom
C321  0.01uF  [SM-7351-CAP-0402]  34.8 36.66 0 top
C322  0.01uF  [SM-7351-CAP-0402]  34.29 38.82 0 bottom
C323  4.7uF  [SM-7351-CAP-0805]  113.79 4.57 90 top
C324  0.01uF  [SM-7351-CAP-0402]  34.29 39.83 0 bottom
C325  4.7uF  [SM-7351-CAP-0805]  103.89 9.02 0 bottom
C326  0.01uF  [SM-7351-CAP-0402]  18.54 39.58 90 bottom
C327  0.01uF  [SM-7351-CAP-0402]  98.17 86.8 90 bottom
C328  0.01uF  [SM-7351-CAP-0402]  91.97 89.26 90 bottom
C329  0.01uF  [SM-7351-CAP-0402]  98.27 81.21 270 bottom
C330  0.01uF  [SM-7351-CAP-0402]  90.93 89.24 90 bottom
C331  0.01uF  [SM-7351-CAP-0402]  96.62 86.29 180 bottom
C332  0.01uF  [SM-7351-CAP-0402]  109.32 77.98 0 bottom
C333  10uF  [SM-7351-CAP-0805]  98.42 96.09 90 bottom
C334  0.01uF  [SM-7351-CAP-0402]  101.6 78.82 270 bottom
C335  0.01uF  [SM-7351-CAP-0402]  104.65 77.45 270 bottom
C336  0.01uF  [SM-7351-CAP-0402]  102.62 78.82 270 bottom
C337  0.01uF  [SM-7351-CAP-0402]  105.77 77.5 270 bottom
C338  0.01uF  [SM-7351-CAP-0402]  105.92 80.78 0 bottom
C339  0.01uF  [SM-7351-CAP-0402]  101.02 76.97 0 bottom
C340  10uF  [SM-7351-CAP-0805]  114.81 77.42 0 bottom
C341  0.01uF  [SM-7351-CAP-0402]  102.41 85.53 90 bottom
C342  0.01uF  [SM-7351-CAP-0402]  109.93 83.6 0 bottom
C343  0.01uF  [SM-7351-CAP-0402]  102.41 83.42 270 bottom
C344  0.01uF  [SM-7351-CAP-0402]  100.36 81.34 90 bottom
C345  0.01uF  [SM-7351-CAP-0402]  99.31 81.34 90 bottom
C346  0.01uF  [SM-7351-CAP-0402]  97.1 76.54 270 bottom
C347  10uF  [SM-7351-CAP-0805]  89.66 75.42 180 bottom
C348  0.01uF  [SM-7351-CAP-0402]  95.02 78.14 90 bottom
C349  0.01uF  [SM-7351-CAP-0402]  99.24 76.54 270 bottom
C350  1uF  [SM-7351-CAP-0402]  96.9 129.24 180 top
C351  0.01uF  [SM-7351-CAP-0402]  96.06 76.54 270 bottom
C352  0.01uF  [SM-7351-CAP-0402]  109.32 76.97 0 bottom
C353  0.01uF  [SM-7351-CAP-0402]  107.06 83.88 270 bottom
C354  10uF  [SM-7351-CAP-0805]  116.2 99.78 90 bottom
C355  0.01uF  [SM-7351-CAP-0402]  105.05 83.98 270 bottom
C356  0.01uF  [SM-7351-CAP-0402]  107.42 85.45 0 bottom
C357  0.01uF  [SM-7351-CAP-0402]  107.42 86.49 0 bottom
C358  0.01uF  [SM-7351-CAP-0402]  105.79 88.09 180 bottom
C359  0.01uF  [SM-7351-CAP-0402]  103.96 86.29 180 bottom
C360  0.01uF  [SM-7351-CAP-0402]  112.27 79.99 0 bottom
C361  10uF  [SM-7351-CAP-0805]  84.33 93.55 180 bottom
C362  0.01uF  [SM-7351-CAP-0402]  109.96 85.76 0 bottom
C363  0.01uF  [SM-7351-CAP-0402]  101.24 86.82 90 bottom
C364  0.01uF  [SM-7351-CAP-0402]  112.26 78.92 0 bottom
C365  0.01uF  [SM-7351-CAP-0402]  109.96 86.9 0 bottom
C367  0.01uF  [SM-7351-CAP-0402]  108.46 88.7 90 bottom
C368  0.01uF  [SM-7351-CAP-0402]  102.54 74.22 270 bottom
C369  0.01uF  [SM-7351-CAP-0402]  117.47 79.08 0 bottom
C370  0.01uF  [SM-7351-CAP-0402]  117.47 80.09 0 bottom
C371  0.01uF  [SM-7351-CAP-0402]  107.04 76.79 270 bottom
C372  0.01uF  [SM-7351-CAP-0402]  98.39 74.22 270 bottom
C373  0.01uF  [SM-7351-CAP-0402]  101.35 89.24 90 bottom
C374  0.01uF  [SM-7351-CAP-0402]  100.46 74.22 270 bottom
C375  10uF  [SM-7351-CAP-0805]  99.54 70.03 0 bottom
C376  0.01uF  [SM-7351-CAP-0402]  96.53 73.9 270 bottom
C377  0.01uF  [SM-7351-CAP-0402]  101.5 74.22 270 bottom
C378  0.01uF  [SM-7351-CAP-0402]  99.2 72.25 0 bottom
C379  0.01uF  [SM-7351-CAP-0402]  102.36 89.24 90 bottom
C380  0.01uF  [SM-7351-CAP-0402]  101.37 83.7 90 bottom
C381  0.01uF  [SM-7351-CAP-0402]  100.58 78.82 270 bottom
C382  2.2uF  [SM-7351-CAP-0402]  136.91 130.64 180 bottom
C383  2.2uF  [SM-7351-CAP-0402]  137.01 129.39 180 bottom
C384  10uF  [SM-7351-CAP-0805]  120.78 86.19 0 bottom
C385  0.01uF  [SM-7351-CAP-0402]  111.38 75.87 0 bottom
C386  0.01uF  [SM-7351-CAP-0402]  107.37 88.7 90 bottom
C387  10uF  [SM-7351-CAP-0805]  99.69 90.04 90 bottom
C388  0.01uF  [SM-7351-CAP-0402]  103.66 81.34 270 bottom
C389  0.01uF  [SM-7351-CAP-0402]  102.41 81.34 90 bottom
C390  0.1uF  [SM-7351-CAP-0402]  94.36 85.04 90 bottom
C391  0.01uF  [SM-7351-CAP-0402]  93.22 85.04 90 bottom
C392  2.2uF  [SM-7351-CAP-0402]  142.75 124.03 180 bottom
C393  0.1uF  [SM-7351-CAP-0402]  91.31 81.53 180 bottom
C394  0.01uF  [SM-7351-CAP-0402]  96.75 81.67 180 bottom
C395  10uF  [SM-7351-CAP-0805]  104.14 97.36 90 bottom
C396  10uF  [SM-7351-CAP-0805]  87.58 89.34 90 bottom
C399  2.2uF  [SM-7351-CAP-0402]  141.22 131.02 180 bottom
C400  0.01uF  [SM-7351-CAP-0402]  96.22 84.92 180 bottom
C401  0.01uF  [SM-7351-CAP-0402]  97.71 83.43 0 bottom
C402  2.2uF  [SM-7351-CAP-0402]  137.67 133.43 90 bottom
C403  0.01uF  [SM-7351-CAP-0402]  88.49 82.78 180 bottom
C404  0.01uF  [SM-7351-CAP-0402]  91.29 84.13 180 bottom
C405  0.01uF  [SM-7351-CAP-0402]  103.38 89.24 90 bottom
C406  0.01uF  [SM-7351-CAP-0402]  96.93 89.13 90 bottom
C407  1uF  [SM-7351-CAP-0402]  144.53 101.05 180 top
C408  0.01uF  [SM-7351-CAP-0402]  147.57 96.47 0 top
C409  0.01uF  [SM-7351-CAP-0402]  147.57 97.49 0 top
C410  0.01uF  [SM-7351-CAP-0402]  149.35 93.17 90 top
C411  100uF  [SM-7351-CAP-SMDCAN]  182.52 126.57 270 bottom
C412  100uF  [SM-7351-CAP-SMDCAN]  182.52 126.57 270 top
C413  10uF  [SM-7351-CAP-0805]  89.66 77.3 180 bottom
C414  10uF  [SM-7351-CAP-0805]  115.7 86.31 0 bottom
C415  0.1uF  [SM-7351-CAP-0402]  153.09 106.14 270 bottom
C416  4.7uF  [SM-7351-CAP-0603]  151.82 106.14 270 bottom
C417  0.1uF  [SM-7351-CAP-0402]  156.01 103.47 270 bottom
C418  22uF  [SM-7351-CAP-0805]  160.6 107.87 90 bottom
C419  22uF  [SM-7351-CAP-0805]  160.6 107.87 90 top
C420  0.01uF  [SM-7351-CAP-0402]  172.97 74.38 90 top
C421  1uF  [SM-7351-CAP-0603]  186.33 81.74 180 bottom
C422  0.01uF  [SM-7351-CAP-0402]  105.79 90.12 180 bottom
C423  0.01uF  [SM-7351-CAP-0402]  105.79 89.11 180 bottom
C424  0.01uF  [SM-7351-CAP-0402]  151.89 98.13 270 top
C425  0.01uF  [SM-7351-CAP-0402]  172.97 69.02 270 top
C426  0.01uF  [SM-7351-CAP-0402]  175.13 81.08 270 bottom
C427  0.01uF  [SM-7351-CAP-0402]  61.21 22.86 180 top
C428  0.01uF  [SM-7351-CAP-0402]  68.71 13.21 0 top
C429  0.01uF  [SM-7351-CAP-0402]  59.26 15.47 180 top
C430  0.01uF  [SM-7351-CAP-0402]  97.79 6.1 180 top
C431  0.1uF  [SM-7351-CAP-0402]  115.44 4.19 90 top
C432  0.1uF  [SM-7351-CAP-0402]  129.67 7.11 270 top
C433  10uF  [SM-7351-CAP-0805]  115.95 8 90 bottom
C434  0.1uF  [SM-7351-CAP-0402]  102.49 12.83 90 bottom
C435  10uF  [SM-7351-CAP-1206]  133.1 8 90 top
C436  0.1uF  [SM-7351-CAP-0402]  60.71 40.51 270 top
C437  0.1uF  [SM-7351-CAP-0402]  59.69 40.51 270 top
C438  0.1uF  [SM-7351-CAP-0402]  74.68 76.66 0 top
C439  0.1uF  [SM-7351-CAP-0402]  74.68 77.68 0 top
C440  100uF  [SM-7351-CAP-SMDCAN]  117.6 53.8 90 bottom
C441  100uF  [SM-7351-CAP-SMDCAN]  70.1 65.49 90 bottom
C442  1uF  [SM-7351-CAP-0402]  103.63 78.82 270 bottom
C443  0.01uF  [SM-7351-CAP-0402]  169.34 81.41 180 bottom
C444  0.01uF  [SM-7351-CAP-0402]  172.57 64.09 270 bottom
C445  1uF  [SM-7351-CAP-0402]  101.37 81.34 90 bottom
C446  1uF  [SM-7351-CAP-0402]  90.55 86.11 90 bottom
C447  1uF  [SM-7351-CAP-0402]  94.11 81.66 180 bottom
C448  0.01uF  [SM-7351-CAP-0402]  171.7 67.65 90 bottom
C449  0.1uF  [SM-7351-CAP-0402]  174.14 5.72 270 bottom
C450  10uF  [SM-7351-CAP-0603]  143.13 127.46 270 bottom
C451  0.01uF  [SM-7351-CAP-0402]  141.86 127.46 270 bottom
C452  10uF  [SM-7351-CAP-0603]  139.19 117.43 270 bottom
C453  0.01uF  [SM-7351-CAP-0402]  132.97 127.36 180 bottom
C454  0.1uF  [SM-7351-CAP-0402]  66.93 75.52 90 top
C455  0.1uF  [SM-7351-CAP-0402]  105.28 137.75 0 top
C456  0.1uF  [SM-7351-CAP-0402]  112.65 137.62 0 top
C457  0.1uF  [SM-7351-CAP-0402]  120.78 137.62 0 top
C458  10uF  [SM-7351-CAP-0805]  157.86 126.83 180 bottom
C459  1uF  [SM-7351-CAP-0603]  157.57 126.74 180 top
C460  0.1uF  [SM-7351-CAP-0402]  156.18 120.52 270 top
C461  10uF  [SM-7351-CAP-0805]  162.85 120.69 270 top
C462  10uF  [SM-7351-CAP-0805]  162.85 125.01 90 top
C463  1.1nF  [SM-7351-CAP-0603]  158.24 115.91 0 top
C464  2.2uF  [SM-7351-CAP-0805]  144.53 134.45 90 bottom
C465  2.2uF  [SM-7351-CAP-0805]  142.62 134.45 90 bottom
C466  2.2uF  [SM-7351-CAP-0805]  132.33 133.05 270 bottom
C467  2.2uF  [SM-7351-CAP-0805]  134.49 133.05 270 bottom
C468  2.2uF  [SM-7351-CAP-0805]  136.53 118.95 180 bottom
C469  0.01uF  [SM-7351-CAP-0402]  57.53 37.72 270 top
C470  0.01uF  [SM-7351-CAP-0402]  57 43.66 180 top
C471  2.2uF  [SM-7351-CAP-0805]  70.61 108.03 180 bottom
C472  2.2uF  [SM-7351-CAP-0805]  75.44 114.13 90 bottom
C473  47uF  [7343]  74.8 89.41 270 bottom
C474  47uF  [7343]  117.86 89.74 0 bottom
C475  47uF  [7343]  128.02 113.49 90 bottom
C476  2.2uF  [SM-7351-CAP-0402]  158.8 106.27 270 bottom
C477  0.1uF  [SM-7351-CAP-0402]  65.91 40.51 270 top
C478  0.1uF  [SM-7351-CAP-0402]  66.93 40.51 270 top
C479  2.2uF  [SM-7351-CAP-0805]  97.92 131.78 0 top
C480  0.01uF  [SM-7351-CAP-0402]  153.16 95.71 180 top
C481  0.01uF  [SM-7351-CAP-0402]  153.16 94.57 180 top
C482  0.01uF  [SM-7351-CAP-0402]  149.73 98 270 top
C483  10uF  [SM-7351-CAP-0805]  84.33 96.09 180 bottom
C484  1uF  [SM-7351-CAP-0402]  150.62 101.05 0 top
C485  0.01uF  [SM-7351-CAP-0402]  96.14 92.79 0 bottom
C486  0.01uF  [SM-7351-CAP-0402]  96.14 91.78 0 bottom
C487  0.01uF  [SM-7351-CAP-0402]  96.14 90.76 0 bottom
C488  0.01uF  [SM-7351-CAP-0402]  146.43 52.53 0 top
C489  0.01uF  [SM-7351-CAP-0402]  141.1 52.53 180 top
C490  0.01uF  [SM-7351-CAP-0402]  144.02 52.53 180 top
C491  0.01uF  [SM-7351-CAP-0402]  139.07 52.53 0 top
C492  22uF  [SM-7351-CAP-0805]  147.96 56.72 0 top
C493  0.01uF  [SM-7351-CAP-0402]  137.03 52.53 0 top
C494  0.01uF  [SM-7351-CAP-0402]  134.75 52.53 0 top
C495  0.01uF  [SM-7351-CAP-0402]  135.26 48.09 270 top
C496  0.01uF  [SM-7351-CAP-0402]  138.81 47.58 180 top
C497  0.01uF  [SM-7351-CAP-0402]  136.78 48.6 0 top
C498  0.01uF  [SM-7351-CAP-0402]  138.81 48.6 180 top
C499  0.01uF  [SM-7351-CAP-0402]  140.08 43.64 180 top
C500  0.01uF  [SM-7351-CAP-0402]  138.05 43.64 0 top
C501  0.01uF  [SM-7351-CAP-0402]  135.64 43.64 180 top
C502  0.01uF  [SM-7351-CAP-0402]  133.73 45.55 270 top
C503  0.1uF  [SM-7351-CAP-0402]  139.95 55.71 270 bottom
C504  0.1uF  [SM-7351-CAP-0402]  140.97 55.71 90 bottom
C505  0.1uF  [SM-7351-CAP-0402]  138.3 55.71 90 bottom
C506  0.01uF  [SM-7351-CAP-0402]  133.73 60.79 270 top
C507  0.01uF  [SM-7351-CAP-0402]  138.05 58.88 0 top
C508  0.01uF  [SM-7351-CAP-0402]  140.08 58.88 180 top
C509  0.01uF  [SM-7351-CAP-0402]  144.53 58.88 0 top
C510  22uF  [SM-7351-CAP-0805]  134.24 56.22 180 top
C511  0.01uF  [SM-7351-CAP-0402]  134.75 67.77 0 top
C512  0.01uF  [SM-7351-CAP-0402]  144.02 67.77 180 top
C513  0.01uF  [SM-7351-CAP-0402]  146.43 67.77 0 top
C514  0.01uF  [SM-7351-CAP-0402]  135.64 58.88 180 top
C515  0.01uF  [SM-7351-CAP-0402]  139.45 67.77 0 top
C516  0.01uF  [SM-7351-CAP-0402]  137.03 67.77 0 top
C517  0.01uF  [SM-7351-CAP-0402]  146.56 58.88 0 top
C518  0.01uF  [SM-7351-CAP-0402]  135.76 63.84 180 top
C519  0.01uF  [SM-7351-CAP-0402]  142.11 58.88 0 top
C520  0.01uF  [SM-7351-CAP-0402]  138.81 62.82 180 top
C521  0.1uF  [SM-7351-CAP-0402]  139.95 70.95 270 bottom
C522  0.1uF  [SM-7351-CAP-0402]  140.97 70.95 90 bottom
C523  0.1uF  [SM-7351-CAP-0402]  142.75 60.58 180 top
C524  0.01uF  [SM-7351-CAP-0402]  104.39 74.25 270 bottom
C525  0.1uF  [SM-7351-CAP-0402]  151 68.28 180 top
C526  0.1uF  [SM-7351-CAP-0402]  149.1 70.95 270 bottom
C527  0.1uF  [SM-7351-CAP-0402]  150.11 70.95 270 bottom
C528  0.1uF  [SM-7351-CAP-0402]  151.51 56.6 270 top
C529  0.1uF  [SM-7351-CAP-0402]  139.95 70.95 270 top
C530  0.1uF  [SM-7351-CAP-0402]  151 67.26 180 bottom
C531  0.1uF  [SM-7351-CAP-0402]  161.54 60.79 0 bottom
C532  10uF  [SM-7351-CAP-0805]  164.21 55.45 0 bottom
C533  10pF  [SM-7351-CAP-0402]  158.37 60.66 90 bottom
C534  10uF  [SM-7351-CAP-0805]  155.32 59.26 90 top
C535  10uF  [SM-7351-CAP-0805]  157.35 59.26 90 top
C536  10uF  [SM-7351-CAP-0805]  155.32 59.26 90 bottom
C537  0.1uF  [SM-7351-CAP-0402]  156.84 58.37 90 bottom
C538  0.1uF  [SM-7351-CAP-0402]  141.99 70.95 270 bottom
C539  0.1uF  [SM-7351-CAP-0402]  151 58.12 180 top
C540  10uF  [SM-7351-CAP-0805]  155.32 55.33 270 bottom
C541  10uF  [SM-7351-CAP-0805]  155.32 55.33 270 top
C542  0.1uF  [SM-7351-CAP-0402]  156.84 56.09 270 bottom
C543  0.001uF  [SM-7351-CAP-0402]  159.51 51.64 270 bottom
C544  0.001uF  [SM-7351-CAP-0402]  158.37 54.18 270 bottom
C545  150uF  [SM-7351-CAP-2917]  11.73 44.96 0 top
C546  4.7uF  [SM-7351-CAP-0603]  6.6 38.44 270 bottom
C547  0.01uF  [SM-7351-CAP-0402]  8.76 41.23 0 top
C548  0.01uF  [SM-7351-CAP-0402]  120.27 81.74 0 bottom
C549  0.1uF  [SM-7351-CAP-0402]  65.41 51.26 0 top
C550  0.01uF  [SM-7351-CAP-0402]  104.9 71.46 270 bottom
C551  0.01uF  [SM-7351-CAP-0402]  106.93 70.06 270 bottom
C552  0.01uF  [SM-7351-CAP-0402]  105.92 74.25 180 bottom
C553  0.01uF  [SM-7351-CAP-0402]  105.92 73.23 180 bottom
C554  0.1uF  [SM-7351-CAP-0402]  37.59 23.37 270 bottom
C555  0.1uF  [SM-7351-CAP-0402]  36.58 23.37 270 bottom
C556  0.1uF  [SM-7351-CAP-0402]  53.98 24.64 270 top
C557  0.1uF  [SM-7351-CAP-0402]  30.23 17.14 0 bottom
C558  0.001uF  [SM-7351-CAP-0402]  30.23 15.88 0 bottom
C559  0.1uF  [SM-7351-CAP-0402]  5.46 32.77 180 top
C560  0.001uF  [SM-7351-CAP-0402]  5.46 34.04 180 top
C562  2.2uF  [SM-7351-CAP-0402]  144.53 122.94 270 bottom
C563  0.1uF  [SM-7351-CAP-0402]  81.91 82.8 180 bottom
C564  0.01uF  [SM-7351-CAP-0402]  99.82 83.44 0 bottom
C565  1uF  [SM-7351-CAP-0402]  81.91 81.41 180 bottom
C566  0.1uF  [SM-7351-CAP-0402]  97.92 78.08 0 bottom
C567  0.01uF  [SM-7351-CAP-0402]  81.28 79.25 180 bottom
C568  1uF  [SM-7351-CAP-0402]  81.28 78.23 180 bottom
C569  0.01uF  [SM-7351-CAP-0402]  161.8 51.18 90 bottom
C570  DNI  [SM-7351-CAP-0402]  161.8 48.89 270 bottom
C571  0.01uF  [SM-7351-CAP-0402]  162.94 40.77 270 bottom
C572  0.01uF  [SM-7351-CAP-0402]  85.98 68.2 270 bottom
C573  0.01uF  [SM-7351-CAP-0402]  91.95 72.77 90 bottom
C574  0.01uF  [SM-7351-CAP-0402]  109.98 84.71 0 bottom
C575  0.01uF  [SM-7351-CAP-0402]  114.81 75.56 0 bottom
C576  0.01uF  [SM-7351-CAP-0402]  88.65 81.66 180 bottom
C577  0.01uF  [SM-7351-CAP-0402]  114.81 74.55 0 bottom
C578  2.2uF  [SM-7351-CAP-0805]  131.79 130.33 180 bottom
D1  -  [SK1545]  167.16 108.03 90 bottom
D2  SMCJ5.0A  [SMCJ26CA]  167.67 114.89 90 top
D3  MMSD103T1  [SOD-123]  39.5 112.86 0 bottom
D4  MMSD103T1  [SOD-123]  61.21 112.86 0 bottom
D5  Green LED  [SM_LED_0805]  179.35 37.46 0 top
D6  Green LED  [SM_LED_0805]  179.35 35.31 0 top
D7  Green LED  [SM_LED_0805]  179.35 33.15 0 top
D8  Green LED  [SM_LED_0805]  179.35 30.99 0 top
D9  Green LED  [SM_LED_0805]  179.35 28.83 0 top
D10  Green LED  [SM_LED_0805]  179.35 26.67 0 top
D11  Green LED  [SM_LED_0805]  179.35 24.51 0 top
D12  Green LED  [SM_LED_0805]  179.35 22.35 0 top
D13  Green LED  [SM_LED_0805]  162.74 91.32 180 top
D14  MBR0520LT1  [MBR0520L]  118.62 5.33 90 bottom
D15  MBR0520LT1  [MBR0520L]  118.62 11.18 270 bottom
D16  Red_Green_Blue_LED  [LED-SM1210]  10.67 4.32 270 top
D17  Red_Green_Blue_LED  [LED-SM1210]  14.86 4.32 270 top
D18  Red_Green_Blue_LED  [LED-SM1210]  18.67 4.32 270 top
D19  Red_Green_Blue_LED  [LED-SM1210]  22.61 4.32 270 top
D20  PMEG2010  [DFN1006D-2]  160.91 123.78 90 top
D22  Red_Green_Blue_LED  [LED-SM1210]  72.9 100.16 270 top
D23  Red_Green_Blue_LED  [LED-SM1210]  69.47 100.16 270 top
D24  TLVH431  [SOT23-3-44M]  38.86 93.6 90 bottom
D25  TLVH431  [SOT23-3-44M]  116.97 128.27 180 bottom
F1  Fuse 8A  [FUSE-0154]  167.51 104.6 180 top
FB1  10  [HF70ACB201209]  48.26 121.75 180 bottom
FB2  10  [HF70ACB201209]  44.2 121.62 180 bottom
FB3  10  [HF70ACB201209]  44.2 118.95 180 bottom
FB4  10  [HF70ACB201209]  44.2 124.29 180 bottom
FB5  10  [HF70ACB201209]  73.02 110.95 180 top
FB6  10  [HF70ACB201209]  65.91 121.87 180 top
FB7  10  [HF70ACB201209]  66.04 119.08 180 top
FB8  10  [HF70ACB201209]  65.91 124.41 180 top
FB9  220OHM2.2A  [SM-7351-IND-0603]  180.37 16.38 180 top
FB10  220OHM2.2A  [SM-7351-IND-0603]  163.75 83.32 90 bottom
FB11  220OHM2.2A  [SM-7351-IND-0603]  163.75 79 270 bottom
FB12  150OHM800mA  [SM-7351-IND-0805]  183.79 20.07 180 bottom
FB13  150OHM800mA  [SM-7351-IND-0805]  23.62 30.82 270 bottom
FB19  150OHM800mA  [SM-7351-IND-0805]  154.69 98.13 180 top
J1  Power Jack RAPC712  [RAPC712]  175.99 111.76 180 top
J1_1  DNI  [HDR4X1RA-108M]  180.83 3.57 270 top
J2  DNI Connector_Screwdown  [CONN_OSTTC02]  186.47 109.35 90 top
J3  RJ-45 10_100Mb  [CNRJ45-1X1WLED]  17.15 135.26 270 top
J4  HEADER 5  [HEADER_5X1]  43.43 78.36 0 top
J5  RJ-45 10_100Mb  [CNRJ45-1X1WLED]  17.15 111.12 270 top
J6  RJ-45 10_100Mb  [CNRJ45-1X1WLED]  17.15 87 270 top
J7  HEADER 5  [HEADER_5X1]  43.31 70.36 0 top
J8  RJ-45 10_100Mb  [CNRJ45-1X1WLED]  17.15 62.23 270 top
J9  HEADER 12x2  [HDR2X12]  159.03 137.11 90 top
J10  RJ-45 Gigabit  [CNRJ45-1X1WLED-598M]  39.24 132.51 180 top
J12  RJ-45 Gigabit  [CNRJ45-1X1WLED-598M]  60.96 132.51 180 top
J14  Conn_DB9F  [NORCOMP_DB9F_SMD]  94.15 2.14 180 top
J15  SCHA5B0200  [SD-MICRO-SCHA5B0300]  90.89 147.64 180 top
J16  XF2M-3215-1A  [CNXF2M-3215-1A]  82.35 121.65 90 bottom
J17  XF2L-0625-1A  [CNXF2L-0625-1A]  51.87 88.26 90 bottom
J18  MIPI JTAG 60pin  [CNQSH030DA]  184.3 89.87 270 top
J19  USB_MicroAB  [ZX62-AB-5PA]  186.38 14.4 90 top
J21  Header_30x2_Female  [HDR2X30-2MM-177M]  101.35 147.02 0 top
J22  10018783-11000TLF  [CN_10018783-11000TLF]  45.63 33.16 0 top
J23  USB3_0_StdA  [CN_LPAF3102NL]  36.24 13.78 0 top
J24  HDMIConnA  [SMD_HDMIA_RA]  62.4 3.58 0 top
J37  Header 15x2 Female  [HDR2X15-344M]  184.94 59.05 270 top
J38  HEADER 5  [HEADER_5X1]  152.78 14.22 270 top
J39  HEADER 3  [HEADER_3X1]  158.75 9.14 270 top
J40  HEADER 2  [HEADER_2X1]  69.34 74.25 0 top
J41  HEADER 2  [HEADER_2X1]  106.55 140.04 90 top
J42  HEADER 2  [HEADER_2X1]  114.05 139.91 90 top
J43  HEADER 2  [HEADER_2X1]  122.05 139.91 90 top
J44  DNI  [HEADER_2X1]  83.57 106.89 0 top
J45  USB_MicroAB  [ZX62-AB-5PA]  4.12 41.1 90 bottom
J46  HEADER 4  [HDR1X4-330M]  168.53 11.51 0 top
J47  HEADER 2  [HEADER_2X1]  64.26 48.85 270 top
J49  HEADER 2  [HEADER_2X1]  50.67 43.05 270 top
J50  HEADER 2  [HEADER_2X1]  14.61 40.89 180 top
L1  4.7uH  [VLCF5020T]  77.98 143.97 270 top
L2  DA2304-AL  [DA2304]  127.76 8.25 180 bottom
L3  NFM21PC474  [FILT-NFM21PC]  28.7 41.23 270 bottom
L11  ACM2012  [ACM2012H]  45.72 24.13 270 bottom
L12  1.0uH  [IND_IHLP1616AB]  151 132.67 0 top
L13  1.0uH  [IND_IHLP1616AB]  151 128.1 0 top
L14  1.0uH  [IND_IHLP1616AB]  151 123.53 0 top
L15  1.0uH  [IND_IHLP1616AB]  128.52 127.21 90 top
L16  1.0uH  [IND_IHLP1616AB]  128.52 121.49 270 top
L17  1.0uH  [IND_IHLP1616AB]  135.51 114.38 270 top
L18  1.0uH  [IND_IHLP1616AB]  128.52 132.92 90 top
L19  1.0uH  [IND_IHLP1616AB]  144.4 114.38 270 top
L20  1.0uH  [IND_IHLP1616AB]  139.95 114.38 270 top
L21  NFM21PC474  [FILT-NFM21PC]  112.73 82.55 90 bottom
L22  4.7uH  [SMD_SLF7055T]  155.12 111.47 0 bottom
L24  NFM21PC474  [FILT-NFM21PC]  108.84 81.87 180 bottom
L25  NFM21PC474  [FILT-NFM21PC]  88.01 85.93 0 bottom
L26  NFM21PC474  [FILT-NFM21PC]  87.88 79.63 0 bottom
L28  3.3uH  [VLCF5020T]  158.88 131.53 0 top
L29  DLW21SN900HQ2L  [FILT-DLW21S]  55.88 20.32 270 top
L30  DLW21SN900HQ2L  [FILT-DLW21S]  58.42 20.32 270 top
L31  DLW21SN900HQ2L  [FILT-DLW21S]  70.87 20.45 270 top
L32  DLW21SN900HQ2L  [FILT-DLW21S]  73.41 20.45 270 top
L33  ACM2012  [ACM2012H]  9.14 40.89 180 bottom
L34  NFM21PC474  [FILT-NFM21PC]  85.47 83.19 180 bottom
L35  NFM21PC474  [FILT-NFM21PC]  80.14 76.07 0 bottom
NOREF  -  []  -29.48 8.76 90 top
NOREF#2  -  [unnamed#2]  185.42 147.32 0 top
NOREF#3  -  [unnamed#3]  27.56 61.8 0 top
NOREF#4  -  []  134.39 29.4 0 top
NOREF#5  -  [unnamed#3]  108.97 42.42 0 top
NOREF#6  -  [unnamed#3]  174.16 14.76 90 top
NOREF#7  -  []  -17.13 -99.99 0 top
NOREF#8  -  [unnamed#3]  148.59 135.97 0 top
NOREF#9  -  [unnamed#3]  62.48 114 0 top
NOREF#10  -  [unnamed#3]  36.96 51.26 0 top
NOREF#11  -  []  190.5 0 90 top
NOREF#12  -  []  -29.48 156.9 0 top
NOREF#13  -  [unnamed#3]  130.56 117.18 0 top
NOREF#14  -  [unnamed#3]  93.6 22.61 0 top
NOREF#15  -  [unnamed#3]  41.1 114.74 0 top
NOREF#16  -  [unnamed#3]  5.08 10.79 0 top
NOREF#17  -  [unnamed#3]  184.18 8.89 0 top
NOREF#18  -  []  152.19 28.25 0 top
NOREF#19  -  [unnamed#3]  172.26 88.78 0 top
NOREF#20  -  [unnamed#3]  156.64 72.39 0 top
NOREF#21  -  [unnamed#3]  35.94 95.97 0 top
NOREF#22  -  [unnamed#3]  4.45 142.96 0 top
NOREF#23  -  [unnamed#2]  5.08 5.08 0 top
NOREF#24  -  [unnamed#3]  29.74 125.66 0 top
NOREF#25  -  []  -17.13 -248.13 90 top
NOREF#26  -  [unnamed#3]  51.46 125.66 0 top
NOREF#27  -  [unnamed#3]  117.22 96.98 0 top
NOREF#28  -  [unnamed#2]  185.42 5.08 0 top
NOREF#29  -  []  54.2 63.91 0 top
NOREF#30  -  [unnamed#3]  123.83 22.1 0 top
NOREF#31  -  [unnamed#3]  78.74 41.78 0 top
NOREF#32  -  [unnamed#3]  27.69 104.35 0 top
NOREF#33  -  [unnamed#3]  27.94 86.82 0 top
NOREF#34  -  []  142.03 84.83 0 top
NOREF#35  -  [unnamed#3]  87.38 66.88 0 top
NOREF#36  -  [unnamed#3]  181.25 143.85 0 top
NOREF#37  -  [unnamed#3]  36.2 75.65 0 top
NOREF#38  -  []  -15.14 -195.3 0 top
NOREF#39  -  [unnamed#2]  5.08 147.32 0 top
NOREF#40  -  []  0 0 0 top
NOREF#41  -  [unnamed#3]  181.25 143.85 180 bottom
NOREF#42  -  [unnamed#3]  184.18 8.89 180 bottom
NOREF#43  -  [unnamed#3]  130.94 70.69 0 bottom
NOREF#44  -  [unnamed#3]  33.66 32.59 270 bottom
NOREF#45  -  [unnamed#3]  25.91 40.47 270 bottom
NOREF#46  -  [unnamed#3]  26.16 123.02 270 bottom
NOREF#47  -  [unnamed#3]  156.84 89.49 0 bottom
NOREF#48  -  [unnamed#3]  5.08 10.79 180 bottom
NOREF#49  -  [unnamed#3]  188.09 63.33 0 bottom
NOREF#50  -  [unnamed#3]  151.89 55.71 0 bottom
NOREF#51  -  [unnamed#3]  131.06 40.72 0 bottom
NOREF#52  -  [unnamed#3]  144.15 102.32 0 bottom
NOREF#53  -  [unnamed#3]  86.49 118.06 180 bottom
NOREF#54  -  [unnamed#3]  4.45 142.96 180 bottom
NOREF#55  -  [unnamed#3]  104.77 135.21 180 bottom
Q1  BSS138  [SOT23-3]  12.45 3.76 90 bottom
Q2  BSS138  [SOT23-3]  19.05 3.76 90 bottom
Q3  BSS138  [SOT23-3]  12.45 10.37 90 bottom
Q4  BSS138  [SOT23-3]  19.05 10.37 90 bottom
Q5  BSS138  [SOT23-3]  12.45 7.07 90 bottom
Q6  BSS138  [SOT23-3]  19.05 7.07 90 bottom
Q7  FDT434P  [SOT223-4]  45.59 112.6 270 bottom
Q8  FDT434P  [SOT223-4]  67.44 111.84 90 top
Q9  BSS138  [SOT23-3]  74.3 148.54 90 top
Q10  BSS138  [SOT23-3]  12.45 20.53 90 bottom
Q11  BSS138  [SOT23-3]  12.45 13.92 90 bottom
Q12  BSS138  [SOT23-3]  19.05 17.23 90 bottom
Q13  BSS138  [SOT23-3]  19.05 13.92 90 bottom
Q14  BSS138  [SOT23-3]  19.05 20.66 90 bottom
Q15  BSS138  [SOT23-3]  12.45 17.23 90 bottom
Q16  BSS138  [SOT23-3]  143.13 13.84 0 top
Q20  BSS138  [SOT23-3]  79.98 103.22 180 bottom
Q21  BSS138  [SOT23-3]  76.55 103.22 180 bottom
Q22  BSS138  [SOT23-3]  73.12 103.22 180 bottom
Q23  BSS138  [SOT23-3]  69.85 94.06 180 bottom
Q24  BSS138  [SOT23-3]  69.72 86.95 180 bottom
Q25  BSS138  [SOT23-3]  69.34 101.17 180 bottom
Q26  MMBT2907A  [SOT23-3-44M]  38.86 97.16 90 bottom
